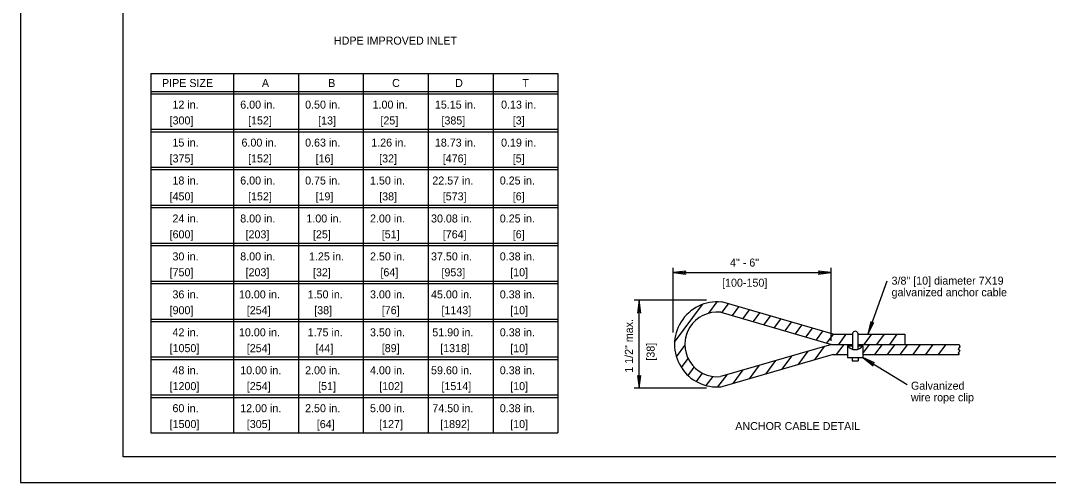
# Model space of a CAD drawing. Extents: x 1083.1 to 1117.1, y 675.4 to 741.4.
# Drawn here: x 1083.13 to 1103.17, y 675.35 to 684.37 of the extents above; entities that cross this region are included whole.
import ezdxf

# ---------------------------------------------------------------- set-up
doc = ezdxf.new("R2010")
doc.units = 0
doc.layers.add('Level 1', color=7, linetype='Continuous')
doc.layers.add('Level 44', color=7, linetype='Continuous')

msp = doc.modelspace()

# ---------------------------------------------------------------- linework, layer by layer
at = {"layer": 'Level 1'}
for p, q in [((1083.126, 697.354), (1083.126, 675.354)), ((1085.665, 683.332), (1093.603, 683.332)), ((1085.665, 683.332), (1085.665, 676.322)), ((1087.278, 683.332), (1087.278, 676.322)), ((1088.543, 683.332), (1088.543, 676.322)), ((1089.808, 683.332), (1089.808, 676.322)), ((1091.073, 683.332), (1091.073, 676.322)), ((1092.338, 683.332), (1092.338, 676.322)), ((1093.603, 683.332), (1093.603, 676.322)), ((1085.665, 682.986), (1093.603, 682.986)), ((1085.665, 682.939), (1093.603, 682.939)), ((1085.665, 682.246), (1093.603, 682.246)), ((1085.665, 682.199), (1093.603, 682.199)), ((1085.665, 681.505), (1093.603, 681.505)), ((1085.665, 681.458), (1093.603, 681.458)), ((1085.665, 680.765), (1093.603, 680.765)), ((1085.665, 680.718), (1093.603, 680.718)), ((1085.665, 680.024), (1093.603, 680.024)), ((1085.665, 679.977), (1093.603, 679.977)), ((1095.846, 678.28), (1095.846, 679.539)), ((1098.929, 678.116), (1098.929, 679.539)), ((1095.846, 679.448), (1098.929, 679.448)), ((1085.665, 679.284), (1093.603, 679.284)), ((1085.665, 679.237), (1093.603, 679.237)), ((1100.016, 679.283), (1099.645, 678.248)), ((1096.502, 678.91), (1095.086, 678.91)), ((1095.186, 677.194), (1095.186, 678.91)), ((1095.877, 678.091), (1096.421, 678.829)), ((1096.544, 678.658), (1096.707, 678.88)), ((1098.966, 678.248), (1096.796, 678.878)), ((1096.805, 678.675), (1096.926, 678.84)), ((1097.009, 678.615), (1097.131, 678.78)), ((1097.213, 678.555), (1097.336, 678.721)), ((1085.665, 678.543), (1093.603, 678.543)), ((1096.778, 678.675), (1096.772, 678.676)), ((1096.778, 678.675), (1098.937, 678.048)), ((1097.418, 678.495), (1097.541, 678.662)), ((1097.622, 678.435), (1097.745, 678.602)), ((1097.826, 678.375), (1097.95, 678.543)), ((1085.665, 678.496), (1093.603, 678.496)), ((1098.03, 678.315), (1098.155, 678.483)), ((1098.235, 678.255), (1098.359, 678.424)), ((1098.439, 678.195), (1098.564, 678.365)), ((1098.643, 678.135), (1098.769, 678.305)), ((1098.847, 678.075), (1098.975, 678.248)), ((1098.966, 678.248), (1099.348, 678.248)), ((1099.076, 678.048), (1099.224, 678.248)), ((1099.348, 678.269), (1099.348, 677.952)), ((1099.448, 678.269), (1099.448, 677.952)), ((1099.448, 678.248), (1100.368, 678.248)), ((1099.573, 678.048), (1099.721, 678.248)), ((1099.822, 678.048), (1099.969, 678.248)), ((1100.07, 678.048), (1100.218, 678.248)), ((1100.368, 678.248), (1100.368, 678.048)), ((1095.913, 677.803), (1096.076, 678.024)), ((1098.937, 678.048), (1096.801, 677.428)), ((1098.286, 677.651), (1098.482, 677.916)), ((1098.602, 677.743), (1098.798, 678.008)), ((1098.937, 678.048), (1099.348, 678.048)), ((1099.034, 677.848), (1099.182, 678.048)), ((1099.248, 678.018), (1099.248, 677.79)), ((1099.248, 678.018), (1099.348, 678.018)), ((1099.448, 678.048), (1101.423, 678.048)), ((1099.448, 678.018), (1099.548, 678.018)), ((1099.548, 677.871), (1099.679, 678.048)), ((1099.548, 678.018), (1099.548, 677.79)), ((1099.78, 677.848), (1099.927, 678.048)), ((1100.028, 677.848), (1100.176, 678.048)), ((1100.277, 677.848), (1100.424, 678.048)), ((1100.525, 677.848), (1100.673, 678.048)), ((1100.774, 677.848), (1100.921, 678.048)), ((1101.022, 677.848), (1101.17, 678.048)), ((1101.437, 677.919), (1101.403, 677.885)), ((1101.441, 678.003), (1101.408, 677.964)), ((1101.408, 677.964), (1101.437, 677.919)), ((1101.423, 678.048), (1101.441, 678.003)), ((1085.665, 677.803), (1093.603, 677.803)), ((1085.665, 677.756), (1093.603, 677.756)), ((1096.009, 677.596), (1096.139, 677.772)), ((1098.966, 677.848), (1096.796, 677.219)), ((1097.654, 677.468), (1097.849, 677.733)), ((1097.97, 677.559), (1098.166, 677.824)), ((1098.966, 677.848), (1099.248, 677.848)), ((1099.248, 677.79), (1099.548, 677.79)), ((1099.338, 677.79), (1099.338, 677.727)), ((1099.338, 677.727), (1099.458, 677.727)), ((1099.458, 677.79), (1099.458, 677.727)), ((1099.548, 677.848), (1101.423, 677.848)), ((1099.548, 677.79), (1100.408, 677.263)), ((1101.403, 677.885), (1101.423, 677.848)), ((1096.142, 677.439), (1096.261, 677.601)), ((1097.022, 677.284), (1097.217, 677.549)), ((1097.338, 677.376), (1097.533, 677.641)), ((1096.303, 677.321), (1096.424, 677.484)), ((1096.495, 677.244), (1096.626, 677.422)), ((1096.723, 677.217), (1096.901, 677.457)), ((1096.801, 677.428), (1096.772, 677.42)), ((1096.502, 677.194), (1095.086, 677.194)), ((1085.665, 677.062), (1093.603, 677.062)), ((1085.665, 677.015), (1093.603, 677.015)), ((1085.665, 676.322), (1093.603, 676.322)), ((1083.126, 675.354), (1117.126, 675.354))]:
    msp.add_line(p, q, dxfattribs=at)
msp.add_lwpolyline([(1085.126, 696.854), (1116.626, 696.854), (1116.626, 675.854), (1085.126, 675.854)], close=True, dxfattribs=at)
for centre, radius, start, end in [((1096.707, 678.048), 0.831, 84.0888, 275.9112), ((1096.707, 678.048), 0.631, 84.0849, 275.9151), ((1096.707, 678.048), 0.631, 156.8864, 171.7595), ((1099.398, 678.251), 0.0532, 20.0676, 159.9324), ((1099.398, 678.136), 0.19, 218.0188, 321.9812)]:
    msp.add_arc(centre, radius, start, end, dxfattribs=at)
at = {"layer": 'Level 44'}
for p, q in [((1096.096, 679.479), (1095.846, 679.448)), ((1095.846, 679.448), (1096.096, 679.417)), ((1098.929, 679.448), (1098.679, 679.479)), ((1098.679, 679.417), (1098.929, 679.448)), ((1095.186, 678.91), (1095.155, 678.66)), ((1095.218, 678.66), (1095.186, 678.91)), ((1099.7, 678.494), (1099.645, 678.248)), ((1099.645, 678.248), (1099.759, 678.473)), ((1099.777, 677.686), (1099.548, 677.79)), ((1099.548, 677.79), (1099.745, 677.633)), ((1095.155, 677.444), (1095.186, 677.194)), ((1095.186, 677.194), (1095.218, 677.444))]:
    msp.add_line(p, q, dxfattribs=at)
for centre, radius, start, end in [((1096.096, 679.448), 0.0312, 90, 270), ((1098.679, 679.448), 0.0312, 270, 90), ((1095.186, 678.66), 0.0312, 0, 180), ((1099.73, 678.483), 0.0312, 160.276, 340.276), ((1099.761, 677.66), 0.0313, 58.4703, 238.4703), ((1095.186, 677.444), 0.0312, 180, 0)]:
    msp.add_arc(centre, radius, start, end, dxfattribs=at)

# ---------------------------------------------------------------- texts
at = {"layer": 'Level 1'}
for s, p in [('HDPE IMPROVED INLET', (1089.236, 683.898)), ('PIPE SIZE', (1085.884, 683.071)), ('A', (1087.831, 683.071)), ('B', (1089.124, 683.071)), ('C', (1090.37, 683.071)), ('D', (1091.598, 683.071)), ('T', (1092.91, 683.071)), ('12 in.', (1086.088, 682.649)), ('6.00 in.', (1087.409, 682.649)), ('0.50 in.', (1088.674, 682.649)), ('1.00 in.', (1089.989, 682.649)), ('15.15 in.', (1091.204, 682.649)), ('0.13 in.', (1092.494, 682.649)), ('[300]', (1086.032, 682.34)), ('[152]', (1087.562, 682.34)), ('[13]', (1088.928, 682.339)), ('[25]', (1090.142, 682.34)), ('[385]', (1091.332, 682.34)), ('[3]', (1092.722, 682.34)), ('15 in.', (1086.088, 681.908)), ('6.00 in.', (1087.434, 681.908)), ('0.63 in.', (1088.674, 681.908)), ('1.26 in.', (1089.964, 681.908)), ('18.73 in.', (1091.204, 681.908)), ('0.19 in.', (1092.494, 681.908)), ('[375]', (1086.032, 681.599)), ('[152]', (1087.562, 681.599)), ('[16]', (1088.878, 681.599)), ('[32]', (1090.117, 681.599)), ('[476]', (1091.357, 681.599)), ('[5]', (1092.722, 681.599)), ('18 in.', (1086.088, 681.168)), ('6.00 in.', (1087.409, 681.168)), ('0.75 in.', (1088.674, 681.168)), ('1.50 in.', (1089.939, 681.168)), ('22.57 in.', (1091.154, 681.168)), ('0.25 in.', (1092.469, 681.168)), ('[450]', (1086.032, 680.859)), ('[152]', (1087.562, 680.859)), ('[19]', (1088.877, 680.859)), ('[38]', (1090.118, 680.858)), ('[573]', (1091.357, 680.859)), ('[6]', (1092.722, 680.859)), ('24 in.', (1086.088, 680.427)), ('8.00 in.', (1087.409, 680.427)), ('1.00 in.', (1088.699, 680.427)), ('2.00 in.', (1089.939, 680.427)), ('30.08 in.', (1091.129, 680.427)), ('0.25 in.', (1092.469, 680.427)), ('[600]', (1086.032, 680.118)), ('[203]', (1087.513, 680.118)), ('[25]', (1088.827, 680.118)), ('[51]', (1090.168, 680.118)), ('[764]', (1091.358, 680.118)), ('[6]', (1092.722, 680.118)), ('30 in.', (1086.088, 679.687)), ('8.00 in.', (1087.409, 679.687)), ('1.25 in.', (1088.749, 679.687)), ('2.50 in.', (1089.939, 679.687)), ('37.50 in.', (1091.129, 679.687)), ('0.38 in.', (1092.469, 679.687)), ('4" - 6"', (1096.958, 679.567)), ('[750]', (1086.032, 679.378)), ('[203]', (1087.513, 679.378)), ('[32]', (1088.827, 679.377)), ('[64]', (1090.142, 679.378)), ('[953]', (1091.332, 679.377)), ('[10]', (1092.672, 679.378)), ('[100-150]', (1096.803, 679.174)), ('3/8" [10] diameter 7X19', (1100.107, 679.214)), ('galvanized anchor cable', (1100.107, 678.988)), ('36 in.', (1086.088, 678.946)), ('10.00 in.', (1087.384, 678.946)), ('1.50 in.', (1088.724, 678.946)), ('3.00 in.', (1089.939, 678.946)), ('45.00 in.', (1091.129, 678.946)), ('0.38 in.', (1092.469, 678.946)), ('[900]', (1086.032, 678.637)), ('[254]', (1087.537, 678.637)), ('[38]', (1088.852, 678.637)), ('[76]', (1090.168, 678.637)), ('[1143]', (1091.332, 678.637)), ('[10]', (1092.672, 678.637)), ('42 in.', (1086.088, 678.206)), ('10.00 in.', (1087.384, 678.206)), ('1.75 in.', (1088.724, 678.206)), ('3.50 in.', (1089.939, 678.206)), ('51.90 in.', (1091.154, 678.206)), ('0.38 in.', (1092.469, 678.206)), ('[1050]', (1086.032, 677.897)), ('[254]', (1087.537, 677.896)), ('[44]', (1088.878, 677.896)), ('[89]', (1090.168, 677.897)), ('[1318]', (1091.307, 677.897)), ('[10]', (1092.672, 677.896)), ('48 in.', (1086.088, 677.465)), ('10.00 in.', (1087.409, 677.465)), ('2.00 in.', (1088.674, 677.465)), ('4.00 in.', (1089.939, 677.465)), ('59.60 in.', (1091.129, 677.465)), ('0.38 in.', (1092.469, 677.465)), ('[1200]', (1086.032, 677.156)), ('[254]', (1087.537, 677.156)), ('[51]', (1088.927, 677.156)), ('[102]', (1090.118, 677.156)), ('[1514]', (1091.332, 677.156)), ('[10]', (1092.672, 677.156)), ('Galvanized', (1100.485, 677.164)), ('wire rope clip', (1100.485, 676.938)), ('60 in.', (1086.088, 676.725)), ('12.00 in.', (1087.409, 676.725)), ('2.50 in.', (1088.674, 676.725)), ('5.00 in.', (1089.939, 676.725)), ('74.50 in.', (1091.154, 676.725)), ('0.38 in.', (1092.469, 676.725)), ('[1500]', (1086.032, 676.416)), ('[305]', (1087.537, 676.416)), ('[64]', (1088.902, 676.415)), ('[127]', (1090.117, 676.416)), ('[1892]', (1091.307, 676.416)), ('[10]', (1092.672, 676.416)), ('ANCHOR CABLE DETAIL', (1097.06, 676.377))]:
    msp.add_text(s, height=0.156, dxfattribs=at).set_placement(p)
for s, p in [('1 1/2" max.', (1095.064, 677.495)), ('[38]', (1095.487, 677.732))]:
    msp.add_text(s, height=0.156, rotation=90, dxfattribs=at).set_placement(p)

doc.saveas('drawing.dxf')
